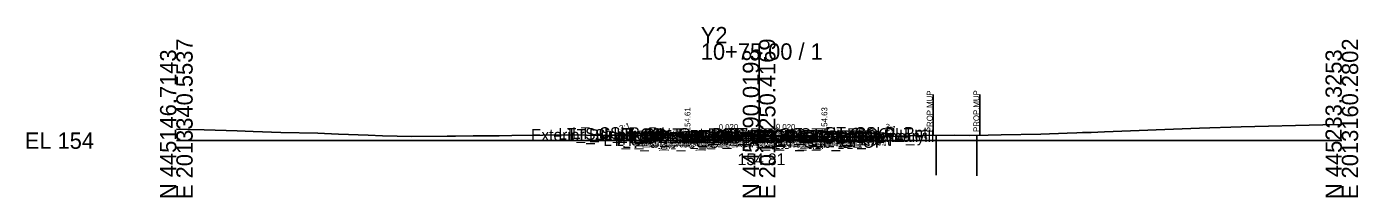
# Model space of a CAD drawing. Extents: x -26 to 203, y -10 to 6017.
# Drawn here: x -25.7 to 202.8, y 1490.3 to 1519.5 of the extents above; entities that cross this region are included whole.
import ezdxf

# ---------------------------------------------------------------- set-up
doc = ezdxf.new("R2010")
doc.units = 0
for name, color, linetype in [('Default', 7, 'Continuous'), ('Exist CMT Pavement', 7, 'Continuous'), ('Exist Cross Section Cell', 7, 'Continuous'), ('Exist XS Center Line Elevation Label', 7, 'Continuous'), ('Exist XS Ground Line', 7, 'Continuous'), ('Prop CMT Conc Surface', 7, 'Continuous'), ('Prop CMT Concrete Structures', 7, 'Continuous'), ('Prop CMT Pvmt Course 1', 7, 'Continuous'), ('Prop CMT Pvmt Course 1 CG', 7, 'Continuous'), ('Prop CMT Pvmt Course 1 Wedge', 7, 'Continuous'), ('Prop CMT Pvmt Course 2', 7, 'Continuous'), ('Prop CMT Pvmt Course 3', 7, 'Continuous'), ('Prop CMT Pvmt Surface', 7, 'Continuous'), ('Prop CMT Pvmt Wedge Surface 1', 7, 'Continuous'), ('Prop CMT Pvmt Wedge Surface 2', 7, 'Continuous'), ('Prop CMT Pvmt Wedge Surface 3', 7, 'Continuous'), ('Prop CMT Slope Grass', 7, 'Continuous'), ('Prop CMT Subgrade Earthwork', 7, 'Continuous'), ('Prop XS Earthwork Shape', 7, 'Continuous'), ('Prop XS Hydro Elevations', 7, 'Continuous'), ('Prop XS Label Text', 7, 'Continuous'), ('Prop XS SE Text', 7, 'Continuous'), ('Prop XS Side Slope Text', 7, 'Continuous'), ('Scratch_Level_0', 7, 'Continuous'), ('Scratch_Level_1', 7, 'Continuous')]:
    doc.layers.add(name, color=color, linetype=linetype)

msp = doc.modelspace()

# ---------------------------------------------------------------- linework, layer by layer
at = {"layer": 'Exist CMT Pavement'}
msp.add_lwpolyline([(90.72, 1500.59), (90.94, 1500.59), (99.64, 1500.82), (100, 1500.81), (104.93, 1500.73), (107.67, 1500.69)], dxfattribs=at)
at = {"layer": 'Exist Cross Section Cell'}
for p, q in [((100, 1500), (100, 1516.65)), ((0, 1500), (100, 1500)), ((100, 1500), (200, 1500))]:
    msp.add_line(p, q, dxfattribs=at)
at = {"layer": 'Exist XS Ground Line'}
msp.add_lwpolyline([(0, 1501.97), (2.09, 1501.9), (4.75, 1501.83), (10.45, 1501.66), (13.19, 1501.54), (17.94, 1501.37), (24.28, 1501.27), (25.44, 1501.21), (27.84, 1501.13), (32.93, 1500.94), (35.38, 1500.84), (40.43, 1500.7), (46.47, 1500.74), (47.92, 1500.77), (50.94, 1500.82), (55.42, 1500.85), (57.57, 1500.86), (62.91, 1500.96), (68.66, 1500.97), (70.41, 1500.93), (75.97, 1500.87), (84.35, 1500.89), (88.04, 1500.8), (89.29, 1500.56), (90.94, 1500.59), (99.64, 1500.82), (100, 1500.81), (104.93, 1500.73), (112.07, 1500.62), (113.04, 1500.72), (114.25, 1500.61), (116.91, 1500.59), (117.72, 1500.59), (128.06, 1500.86), (133.45, 1500.91), (136.07, 1500.9), (139.34, 1500.93), (141.57, 1500.98), (148.34, 1501.11), (152.86, 1501.27), (154.53, 1501.35), (155.52, 1501.38), (156.12, 1501.41), (156.43, 1501.42), (157.01, 1501.39), (159.25, 1501.52), (175.56, 1502.13), (182.74, 1502.38), (196.72, 1502.68), (200, 1502.76)], dxfattribs=at)
at = {"layer": 'Prop CMT Conc Surface'}
for points in [[(87.72, 1500.61), (87.72, 1501.11), (87.22, 1501.11)], [(89.72, 1500.73), (87.72, 1500.61)], [(109.21, 1500.75), (111.21, 1500.63)], [(111.21, 1500.63), (111.22, 1501.13), (111.72, 1501.13)]]:
    msp.add_lwpolyline(points, dxfattribs=at)
at = {"layer": 'Prop CMT Concrete Structures'}
for points in [[(89.72, 1500.73), (87.72, 1500.61), (87.72, 1501.11), (87.22, 1501.11)], [(87.22, 1501.11), (87.22, 1500.1), (89.72, 1500.15)], [(89.72, 1500.15), (89.72, 1500.73)], [(109.21, 1500.75), (111.21, 1500.63), (111.22, 1501.13), (111.72, 1501.13)], [(111.72, 1501.13), (111.71, 1500.12), (109.21, 1500.17)], [(109.21, 1500.17), (109.21, 1500.75)]]:
    msp.add_lwpolyline(points, dxfattribs=at)
at = {"layer": 'Prop CMT Pvmt Course 1'}
for points in [[(99.98, 1500.94), (89.72, 1500.73)], [(89.72, 1500.73), (89.72, 1500.48)], [(89.72, 1500.48), (90.72, 1500.5)], [(90.72, 1500.63), (99.98, 1500.81)], [(90.72, 1500.5), (90.72, 1500.63)], [(99.98, 1500.69), (99.98, 1500.94)], [(99.98, 1500.94), (109.21, 1500.75)], [(99.98, 1500.69), (99.98, 1500.94)], [(99.98, 1500.81), (99.98, 1500.69), (99.98, 1500.69)], [(107.67, 1500.66), (99.98, 1500.81)], [(99.98, 1500.81), (99.98, 1500.69), (99.98, 1500.69)], [(107.67, 1500.53), (107.67, 1500.66)], [(109.21, 1500.5), (107.67, 1500.53)], [(109.21, 1500.75), (109.21, 1500.5)]]:
    msp.add_lwpolyline(points, dxfattribs=at)
at = {"layer": 'Prop CMT Pvmt Course 1 CG'}
for points in [[(89.72, 1500.15), (86.72, 1500.09), (86.38, 1499.75)], [(86.38, 1499.75), (89.72, 1499.82)], [(89.72, 1499.82), (89.72, 1500.15)], [(109.21, 1500.17), (112.21, 1500.11), (112.55, 1499.77)], [(109.21, 1499.84), (109.21, 1500.17)], [(112.55, 1499.77), (109.21, 1499.84)]]:
    msp.add_lwpolyline(points, dxfattribs=at)
at = {"layer": 'Prop CMT Pvmt Course 1 Wedge'}
for points in [[(90.72, 1500.63), (90.94, 1500.63), (98.12, 1500.78)], [(98.12, 1500.78), (90.94, 1500.59), (90.72, 1500.59)], [(90.72, 1500.59), (90.72, 1500.63)], [(99.98, 1500.81), (99.89, 1500.81)], [(99.89, 1500.81), (99.98, 1500.81)], [(99.98, 1500.81), (99.98, 1500.81)], [(99.98, 1500.81), (100.74, 1500.8)], [(100.74, 1500.8), (99.98, 1500.81)], [(99.98, 1500.81), (99.98, 1500.81)]]:
    msp.add_lwpolyline(points, dxfattribs=at)
at = {"layer": 'Prop CMT Pvmt Course 2'}
for points in [[(90.72, 1500.5), (89.72, 1500.48)], [(89.72, 1500.48), (89.72, 1500.15)], [(89.72, 1500.15), (90.72, 1500.17)], [(90.72, 1500.17), (90.72, 1500.5)], [(107.67, 1500.2), (107.67, 1500.53)], [(107.67, 1500.53), (109.21, 1500.5)], [(109.21, 1500.17), (107.67, 1500.2)], [(109.21, 1500.5), (109.21, 1500.17)]]:
    msp.add_lwpolyline(points, dxfattribs=at)
at = {"layer": 'Prop CMT Pvmt Course 3'}
for points in [[(90.72, 1500.17), (89.72, 1500.15)], [(89.72, 1500.15), (89.72, 1499.82)], [(89.72, 1499.82), (90.72, 1499.84)], [(90.72, 1499.84), (90.72, 1500.17)], [(107.67, 1500.2), (109.21, 1500.17)], [(107.67, 1499.87), (107.67, 1500.2)], [(109.21, 1499.84), (107.67, 1499.87)], [(109.21, 1500.17), (109.21, 1499.84)]]:
    msp.add_lwpolyline(points, dxfattribs=at)
at = {"layer": 'Prop CMT Pvmt Surface'}
for points in [[(99.98, 1500.94), (89.72, 1500.73)], [(99.98, 1500.94), (109.21, 1500.75)]]:
    msp.add_lwpolyline(points, dxfattribs=at)
at = {"layer": 'Prop CMT Pvmt Wedge Surface 1'}
for points in [[(89.72, 1500.48), (89.72, 1500.73)], [(90.72, 1500.5), (89.72, 1500.48)], [(99.98, 1500.81), (90.72, 1500.63)], [(90.72, 1500.63), (90.72, 1500.5)], [(99.98, 1500.81), (107.67, 1500.66)], [(107.67, 1500.66), (107.67, 1500.53)], [(107.67, 1500.53), (109.21, 1500.5)], [(109.21, 1500.5), (109.21, 1500.75)]]:
    msp.add_lwpolyline(points, dxfattribs=at)
at = {"layer": 'Prop CMT Pvmt Wedge Surface 2'}
for points in [[(89.72, 1500.48), (89.72, 1500.73)], [(99.98, 1500.69), (89.72, 1500.48)], [(99.98, 1500.69), (109.21, 1500.5)], [(109.21, 1500.5), (109.21, 1500.75)]]:
    msp.add_lwpolyline(points, dxfattribs=at)
at = {"layer": 'Prop CMT Pvmt Wedge Surface 3'}
for points in [[(89.72, 1500.15), (89.72, 1500.73)], [(99.98, 1500.35), (89.72, 1500.15)], [(99.98, 1500.35), (109.21, 1500.17)], [(109.21, 1500.17), (109.21, 1500.75)]]:
    msp.add_lwpolyline(points, dxfattribs=at)
at = {"layer": 'Prop CMT Slope Grass'}
for points in [[(87.22, 1501.11), (77.72, 1501.3), (76.42, 1500.87)], [(111.72, 1501.13), (121.22, 1501.32), (123.01, 1500.73)]]:
    msp.add_lwpolyline(points, dxfattribs=at)
at = {"layer": 'Prop CMT Subgrade Earthwork'}
for points in [[(89.72, 1499.82), (86.38, 1499.75), (84.97, 1501.16)], [(90.72, 1499.84), (89.72, 1499.82)], [(90.72, 1499.84), (90.72, 1500.59)], [(107.67, 1499.87), (107.67, 1500.69)], [(107.67, 1499.87), (109.21, 1499.84)], [(109.21, 1499.84), (112.55, 1499.77), (113.96, 1501.18)]]:
    msp.add_lwpolyline(points, dxfattribs=at)
at = {"layer": 'Prop XS Earthwork Shape'}
for points in [[(85.26, 1500.87), (84.97, 1501.16), (77.72, 1501.3), (76.42, 1500.87), (84.35, 1500.89)], [(85.26, 1500.87), (84.97, 1501.16), (77.72, 1501.3), (76.42, 1500.87), (84.35, 1500.89)], [(85.26, 1500.87), (84.97, 1501.16), (77.72, 1501.3), (76.42, 1500.87), (84.35, 1500.89)], [(85.26, 1500.87), (84.97, 1501.16), (77.72, 1501.3), (76.42, 1500.87), (84.35, 1500.89)], [(85.26, 1500.87), (87.22, 1500.82), (87.22, 1500.1), (89.72, 1500.15), (89.72, 1500.57), (90.72, 1500.59), (90.72, 1499.84), (89.72, 1499.82), (86.38, 1499.75)], [(85.26, 1500.87), (87.22, 1500.82), (87.22, 1500.1), (89.72, 1500.15), (89.72, 1500.57), (90.72, 1500.59), (90.72, 1499.84), (89.72, 1499.82), (86.38, 1499.75)], [(85.26, 1500.87), (87.22, 1500.82), (87.22, 1500.1), (89.72, 1500.15), (89.72, 1500.57), (90.72, 1500.59), (90.72, 1499.84), (89.72, 1499.82), (86.38, 1499.75)], [(85.26, 1500.87), (87.22, 1500.82), (87.22, 1500.1), (89.72, 1500.15), (89.72, 1500.57), (90.72, 1500.59), (90.72, 1499.84), (89.72, 1499.82), (86.38, 1499.75)], [(87.72, 1500.61), (87.72, 1500.81), (87.22, 1500.82), (87.22, 1500.1), (89.72, 1500.15), (89.72, 1500.57), (89.29, 1500.56), (88.71, 1500.67)], [(87.72, 1500.61), (87.72, 1500.81), (87.22, 1500.82), (87.22, 1500.1), (89.72, 1500.15), (89.72, 1500.57), (89.29, 1500.56), (88.71, 1500.67)], [(87.72, 1500.61), (87.72, 1500.81), (87.22, 1500.82), (87.22, 1500.1), (89.72, 1500.15), (89.72, 1500.57), (89.29, 1500.56), (88.71, 1500.67)], [(87.72, 1500.61), (87.72, 1500.81), (87.22, 1500.82), (87.22, 1500.1), (89.72, 1500.15), (89.72, 1500.57), (89.29, 1500.56), (88.71, 1500.67)], [(87.72, 1500.61), (87.72, 1500.81), (88.04, 1500.8), (88.71, 1500.67)], [(87.72, 1500.61), (87.72, 1500.81), (88.04, 1500.8), (88.71, 1500.67)], [(87.72, 1500.61), (87.72, 1500.81), (88.04, 1500.8), (88.71, 1500.67)], [(87.72, 1500.61), (87.72, 1500.81), (88.04, 1500.8), (88.71, 1500.67)], [(107.67, 1499.87), (107.67, 1500.69), (109.21, 1500.66), (109.21, 1500.17), (111.71, 1500.12), (111.71, 1500.62), (112.07, 1500.62), (113.04, 1500.72), (113.46, 1500.68), (112.55, 1499.77), (109.21, 1499.84)], [(107.67, 1499.87), (107.67, 1500.69), (109.21, 1500.66), (109.21, 1500.17), (111.71, 1500.12), (111.71, 1500.62), (112.07, 1500.62), (113.04, 1500.72), (113.46, 1500.68), (112.55, 1499.77), (109.21, 1499.84)], [(107.67, 1499.87), (107.67, 1500.69), (109.21, 1500.66), (109.21, 1500.17), (111.71, 1500.12), (111.71, 1500.62), (112.07, 1500.62), (113.04, 1500.72), (113.46, 1500.68), (112.55, 1499.77), (109.21, 1499.84)], [(107.67, 1499.87), (107.67, 1500.69), (109.21, 1500.66), (109.21, 1500.17), (111.71, 1500.12), (111.71, 1500.62), (112.07, 1500.62), (113.04, 1500.72), (113.46, 1500.68), (112.55, 1499.77), (109.21, 1499.84)], [(111.71, 1500.12), (109.21, 1500.17), (109.21, 1500.66), (111.21, 1500.63), (111.71, 1500.62)], [(111.71, 1500.12), (109.21, 1500.17), (109.21, 1500.66), (111.21, 1500.63), (111.71, 1500.62)], [(111.71, 1500.12), (109.21, 1500.17), (109.21, 1500.66), (111.21, 1500.63), (111.71, 1500.62)], [(111.71, 1500.62), (111.71, 1500.12), (109.21, 1500.17), (109.21, 1500.66), (111.21, 1500.63)], [(113.46, 1500.68), (113.96, 1501.18), (121.22, 1501.32), (123.01, 1500.73), (117.72, 1500.59), (116.91, 1500.59), (114.25, 1500.61)], [(113.46, 1500.68), (114.25, 1500.61), (116.91, 1500.59), (117.72, 1500.59), (123.01, 1500.73), (121.22, 1501.32), (113.96, 1501.18)], [(113.46, 1500.68), (113.96, 1501.18), (121.22, 1501.32), (123.01, 1500.73), (117.72, 1500.59), (116.91, 1500.59), (114.25, 1500.61)], [(113.46, 1500.68), (113.96, 1501.18), (121.22, 1501.32), (123.01, 1500.73), (117.72, 1500.59), (116.91, 1500.59), (114.25, 1500.61)]]:
    msp.add_lwpolyline(points, close=True, dxfattribs=at)
at = {"layer": 'Prop XS Label Text'}
for p, q in [((129.88, 1507.87), (129.88, 1500.87)), ((137.88, 1507.92), (137.88, 1500.92))]:
    msp.add_line(p, q, dxfattribs=at)
at = {"layer": 'Scratch_Level_1'}
for p, q in [((130.38, 1500.88), (130.38, 1494.09)), ((137.38, 1500.91), (137.38, 1493.98))]:
    msp.add_line(p, q, dxfattribs=at)

# ---------------------------------------------------------------- texts
at = {"layer": 'Default'}
msp.add_text('-', height=0.0001, dxfattribs=at).set_placement((0, 1500))
at = {"layer": 'Exist Cross Section Cell'}
for s, p in [('Y2', (90, 1516.65)), ('10+75.00 / 1', (90, 1513.85)), ('EL 154', (-26, 1498.6))]:
    msp.add_text(s, height=2.8, dxfattribs=at).set_placement(p)
for s, p in [('N 445146.7143', (0, 1490)), ('E 2013340.5537', (2.8, 1490)), ('N 445190.0198', (100, 1490)), ('E 2013250.4169', (102.8, 1490)), ('N 445233.3253', (200, 1490)), ('E 2013160.2802', (202.8, 1490))]:
    msp.add_text(s, height=2.8, rotation=90, dxfattribs=at).set_placement(p)
at = {"layer": 'Exist XS Center Line Elevation Label'}
msp.add_text('154.81', height=2, dxfattribs=at).set_placement((96.32, 1495.81))
at = {"layer": 'Prop XS Hydro Elevations'}
for s, p in [('154.61', (88.22, 1501.61)), ('154.63', (111.71, 1501.63))]:
    msp.add_text(s, height=1, rotation=90, dxfattribs=at).set_placement(p)
at = {"layer": 'Prop XS Label Text'}
for p in [(129.78, 1501.45), (137.78, 1501.49)]:
    msp.add_text('PROP.MUP', height=1, rotation=90, dxfattribs=at).set_placement(p)
at = {"layer": 'Prop XS SE Text'}
for rotation, p in [(1.1458, (93.08, 1501.8)), (358.8553, (102.87, 1501.88))]:
    msp.add_text('0.020', height=1, rotation=rotation, dxfattribs=at).set_placement(p)
at = {"layer": 'Prop XS Side Slope Text'}
for rotation, p in [(18.4334, (76.22, 1501.59)), (341.6111, (121.51, 1502.02))]:
    msp.add_text('3:1', height=1, rotation=rotation, dxfattribs=at).set_placement(p)
at = {"layer": 'Scratch_Level_0'}
for s, p in [('Exterior Boundary', (60.85, 1499.97)), ('LT_Sub_Trench_Out_DLT', (65.54, 1500.16)), ('LT_Slope_Fill', (67.22, 1499.97)), ('LT_CSLP_Pnt', (67.89, 1500.3)), ('LT_CG_Top_Face', (74.98, 1500.11)), ('LT_CG_Top_BOC', (75.5, 1500.11)), ('LT_PV_Sub_Tie_Out', (75.68, 1499.59)), ('LT_CG_Top_Gut', (75.95, 1499.61)), ('LT_PV_OEEOP_EG', (78.26, 1499.59)), ('LT_PV2_OEOT', (79.89, 1499.48)), ('LT_PV2_OEEOP', (80.03, 1499.5)), ('LT_PV1_OEOT', (80.46, 1499.73)), ('LT_PV1_OEEOP', (80.59, 1499.63)), ('RT_PV_IEEOP_EG', (88.12, 1499.81)), ('LT_PV_IEEOP_EG', (88.17, 1499.81)), ('RT_PV2_IEEOP', (89.89, 1499.69)), ('LT_PV2_IEEOP', (89.93, 1499.69)), ('RT_PV1_IEEOP', (90.45, 1499.81)), ('LT_PV1_IEEOP', (90.5, 1499.81)), ('RT_PV_Sub_Tie_Out', (92.55, 1499.68)), ('PV2_PGL', (93.89, 1499.69)), ('PV1_PGL', (94.45, 1499.94)), ('RT_Sub_Trench_Out_DLT', (94.48, 1500.18)), ('RT_PV_OEEOP_EG', (95.16, 1499.68)), ('RT_PV2_OEEOP', (96.93, 1499.53)), ('RT_PV1_OEEOP', (97.49, 1499.66)), ('RT_CG_Top_Face', (98.43, 1500.13)), ('RT_PV2_OEOT', (99.34, 1499.5)), ('RT_CG_Top_Gut', (99.4, 1499.63)), ('RT_PV1_OEOT', (99.91, 1499.75)), ('RT_CG_Top_BOC', (99.95, 1500.13)), ('Exterior Boundary', (106.98, 1499.78)), ('RT_CSLP_Pnt', (111.34, 1500.32)), ('RT_Slope_Fill', (113.31, 1499.78)), ('LT_CG1_Shelf_Out', (73.27, 1499.09)), ('LT_CG_Bot_BOC', (75.53, 1499.1)), ('LT_Sub_OEOP', (76.49, 1498.75)), ('LT_CG_Bot_IE', (79.63, 1499.15)), ('LT_Sub_OEOT', (79.8, 1498.82)), ('LT_PV3_OEOT', (79.89, 1499.15)), ('LT_Sub_OEEOP', (79.93, 1498.84)), ('LT_PV3_OEEOP', (80.03, 1499.17)), ('RT_PV3_IEEOP', (89.89, 1499.35)), ('LT_PV3_IEEOP', (89.93, 1499.35)), ('RT_Sub_OEEOP', (96.83, 1498.87)), ('RT_PV3_OEEOP', (96.93, 1499.2)), ('RT_CG1_Shelf_Out', (98.72, 1499.11)), ('RT_CG_Bot_IE', (99.08, 1499.17)), ('RT_Sub_OEOT', (99.25, 1498.84)), ('RT_PV3_OEOT', (99.34, 1499.17)), ('RT_CG_Bot_BOC', (99.98, 1499.12)), ('RT_Sub_OEOP', (102.62, 1498.77))]:
    msp.add_text(s, height=2, dxfattribs=at).set_placement(p)

doc.saveas('drawing.dxf')
